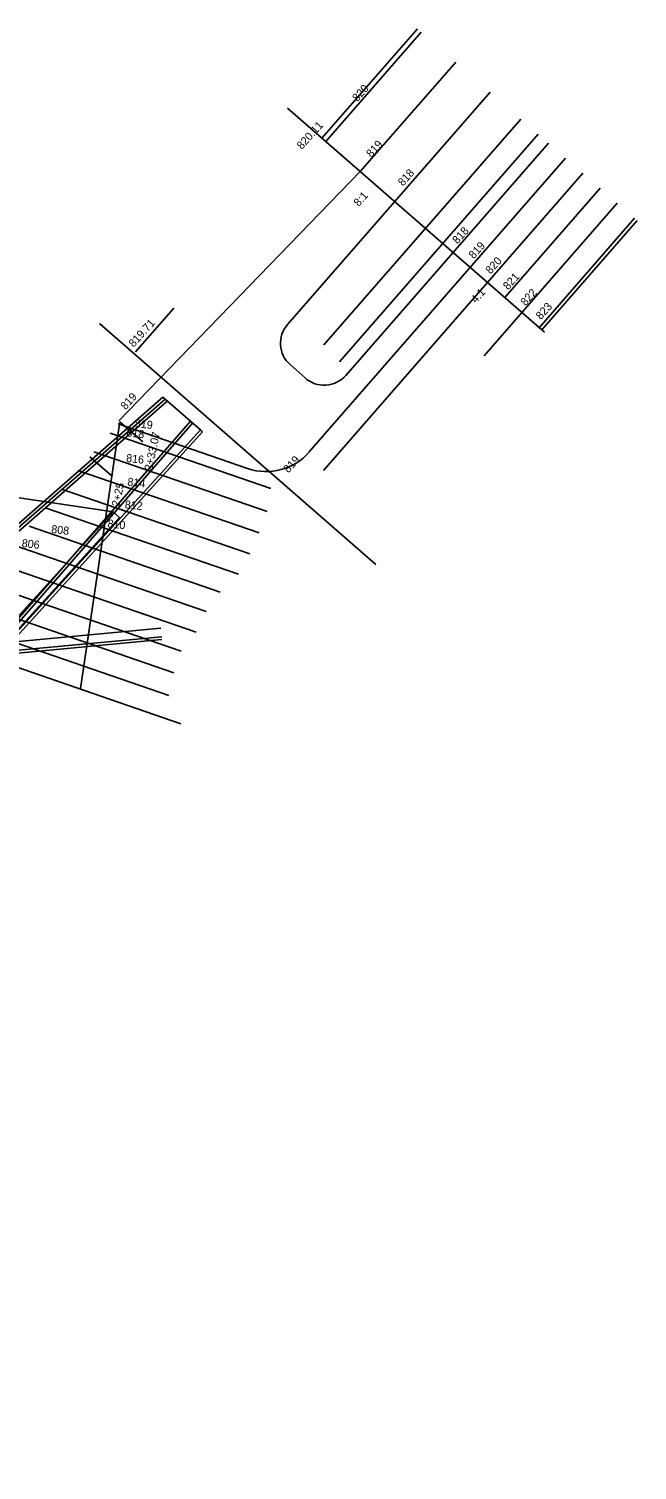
# Model space of a CAD drawing. Extents: x 1465887 to 1476191, y 569684 to 581027.
# Drawn here: x 1470052.7 to 1470159.1, y 573989.8 to 574241.9 of the extents above; entities that cross this region are included whole.
import ezdxf

# ---------------------------------------------------------------- set-up
doc = ezdxf.new("R2010")
doc.units = 0
for name, color, linetype in [('BR_P_Gen_Approach_Slab', 7, 'Continuous'), ('BR_P_Gen_Ground_Slope', 7, 'Continuous'), ('BR_P_Gen_Perforated_Pipe', 7, 'Continuous'), ('BR_P_Gen_Porous_Backfill', 7, 'Continuous'), ('BR_P_Gen_Slope_Protection', 7, 'Continuous'), ('BR_P_Rail_Object', 7, 'Continuous'), ('SC_Scratch1', 7, 'Continuous')]:
    doc.layers.add(name, color=color, linetype=linetype)

msp = doc.modelspace()

# ---------------------------------------------------------------- linework, layer by layer
at = {"layer": 'BR_P_Gen_Approach_Slab'}
msp.add_line((1469928.13, 574178.07), (1470067.44, 574157.44), dxfattribs=at)
at = {"layer": 'BR_P_Gen_Ground_Slope'}
for p, q in [((1470103.98, 574222.77), (1470120.68, 574241.91)), ((1470104.65, 574222.19), (1470121.34, 574241.33)), ((1470110.68, 574216.93), (1470127.37, 574236.07)), ((1470097.97, 574190.2), (1470133.4, 574230.81)), ((1470108.13, 574181.28), (1470143.59, 574221.92)), ((1470101.77, 574167.9), (1470146.6, 574219.29)), ((1470068.44, 574173.34), (1470110.68, 574216.93)), ((1470104.26, 574164.67), (1470149.62, 574216.66)), ((1470135.94, 574194.9), (1470152.63, 574214.03)), ((1470132.37, 574184.72), (1470155.64, 574211.4)), ((1470141.96, 574189.64), (1470158.66, 574208.77)), ((1470071.39, 574185.41), (1470078.06, 574193.05)), ((1470101.03, 574180.84), (1470098.41, 574183.19)), ((1470068.36, 574172.8), (1470090.98, 574165.01)), ((1470066.94, 574171.17), (1470095.06, 574161.49)), ((1470064.1, 574167.92), (1470094.39, 574157.49)), ((1470061.26, 574164.66), (1470093, 574153.74)), ((1470058.42, 574161.41), (1470091.35, 574150.08)), ((1470055.59, 574158.16), (1470089.36, 574146.54)), ((1470052.75, 574154.9), (1470086.2, 574143.39)), ((1470049.91, 574151.65), (1470083.71, 574140.02)), ((1470047.07, 574148.4), (1470081.96, 574136.39)), ((1470044.23, 574145.14), (1470079.36, 574133.06)), ((1470041.4, 574141.89), (1470078.05, 574129.27)), ((1470033.76, 574133.13), (1470075.82, 574137.1)), ((1470038.56, 574138.64), (1470077.23, 574125.33)), ((1470031.85, 574130.95), (1470076, 574135.11)), ((1470032.33, 574131.49), (1470075.96, 574135.6)), ((1470035.72, 574135.38), (1470079.31, 574120.38))]:
    msp.add_line(p, q, dxfattribs=at)
for centre, radius, start, end in [((1470101.74, 574186.91), 5, 138.9019, 228.1817), ((1470104.37, 574184.57), 5, 228.1817, 318.9019), ((1470094.23, 574174.47), 10, 251.0087, 318.9019)]:
    msp.add_arc(centre, radius, start, end, dxfattribs=at)
at = {"layer": 'BR_P_Gen_Perforated_Pipe'}
for p, q in [((1470076.51, 574177.1), (1470044.7, 574149.26)), ((1470076.84, 574176.72), (1470044.86, 574148.73)), ((1470043.82, 574130.69), (1470080.98, 574173.29)), ((1470044.02, 574130.16), (1470081.36, 574172.96))]:
    msp.add_line(p, q, dxfattribs=at)
at = {"layer": 'BR_P_Gen_Porous_Backfill'}
for p, q in [((1470076.18, 574177.48), (1470044.55, 574149.79)), ((1470082.72, 574171.78), (1470076.18, 574177.48))]:
    msp.add_line(p, q, dxfattribs=at)
at = {"layer": 'BR_P_Gen_Slope_Protection'}
for p, q in [((1470044.4, 574129.59), (1470082.72, 574171.78)), ((1470044.6, 574129.06), (1470083.08, 574171.44)), ((1470082.71, 574171.78), (1470083.08, 574171.44))]:
    msp.add_line(p, q, dxfattribs=at)
at = {"layer": 'BR_P_Rail_Object'}
for p, q in [((1469915.23, 573989.83), (1470067.44, 574157.44)), ((1470067.44, 574157.44), (1470068.55, 574156.43)), ((1469923.07, 573996.23), (1470068.55, 574156.43))]:
    msp.add_line(p, q, dxfattribs=at)
at = {"layer": 'SC_Scratch1'}
for p, q in [((1470097.96, 574228.03), (1470142.88, 574188.84)), ((1470104.33, 574186.66), (1470138.76, 574226.13)), ((1470107.03, 574183.67), (1470141.78, 574223.5)), ((1470142.42, 574189.24), (1470159.11, 574208.38)), ((1470065.09, 574190.35), (1470113.41, 574148.2)), ((1470061.76, 574126.52), (1470068.66, 574173.15)), ((1470072.63, 574169.68), (1470068.66, 574173.15)), ((1470067.33, 574163.6), (1470063.36, 574167.07))]:
    msp.add_line(p, q, dxfattribs=at)

# ---------------------------------------------------------------- texts
at = {"layer": 'BR_P_Gen_Ground_Slope'}
for s, rotation, p in [('820', 47.7564, (1470110.17, 574229.08)), ('820.11', 47.7564, (1470100.46, 574220.71)), ('819', 47.7564, (1470112.61, 574219.32)), ('818', 47.7564, (1470118.14, 574214.3)), ('8:1', 47.7564, (1470110.41, 574210.74)), ('818', 47.7564, (1470127.67, 574204.18)), ('819', 47.7564, (1470130.53, 574201.58)), ('820', 47.7564, (1470133.46, 574198.92)), ('821', 47.7564, (1470136.53, 574196.14)), ('4:1', 47.7564, (1470130.91, 574193.83)), ('822', 47.7564, (1470139.59, 574193.36)), ('823', 47.7564, (1470142.26, 574190.94)), ('819.71', 47.7564, (1470071.05, 574186.13)), ('819', 47.7564, (1470069.64, 574175.17)), ('819', 353.6662, (1470071.2, 574172.25)), ('818', 353.6662, (1470069.73, 574170.63)), ('816', 353.6662, (1470069.68, 574166.18)), ('819', 47.7564, (1470098.11, 574164.14)), ('814', 353.6662, (1470069.9, 574162.03)), ('812', 353.6662, (1470069.44, 574158.07)), ('808', 353.6662, (1470056.58, 574153.75)), ('810', 353.6662, (1470066.42, 574154.73)), ('806', 353.6662, (1470051.42, 574151.3))]:
    msp.add_text(s, height=1.4, rotation=rotation, dxfattribs=at).set_placement(p)
at = {"layer": 'SC_Scratch1'}
for s, p in [('2+33.07', (1470074.25, 574164.55)), ('2+25', (1470068.53, 574158.25))]:
    msp.add_text(s, height=1.4, rotation=77.7564, dxfattribs=at).set_placement(p)

doc.saveas('drawing.dxf')
